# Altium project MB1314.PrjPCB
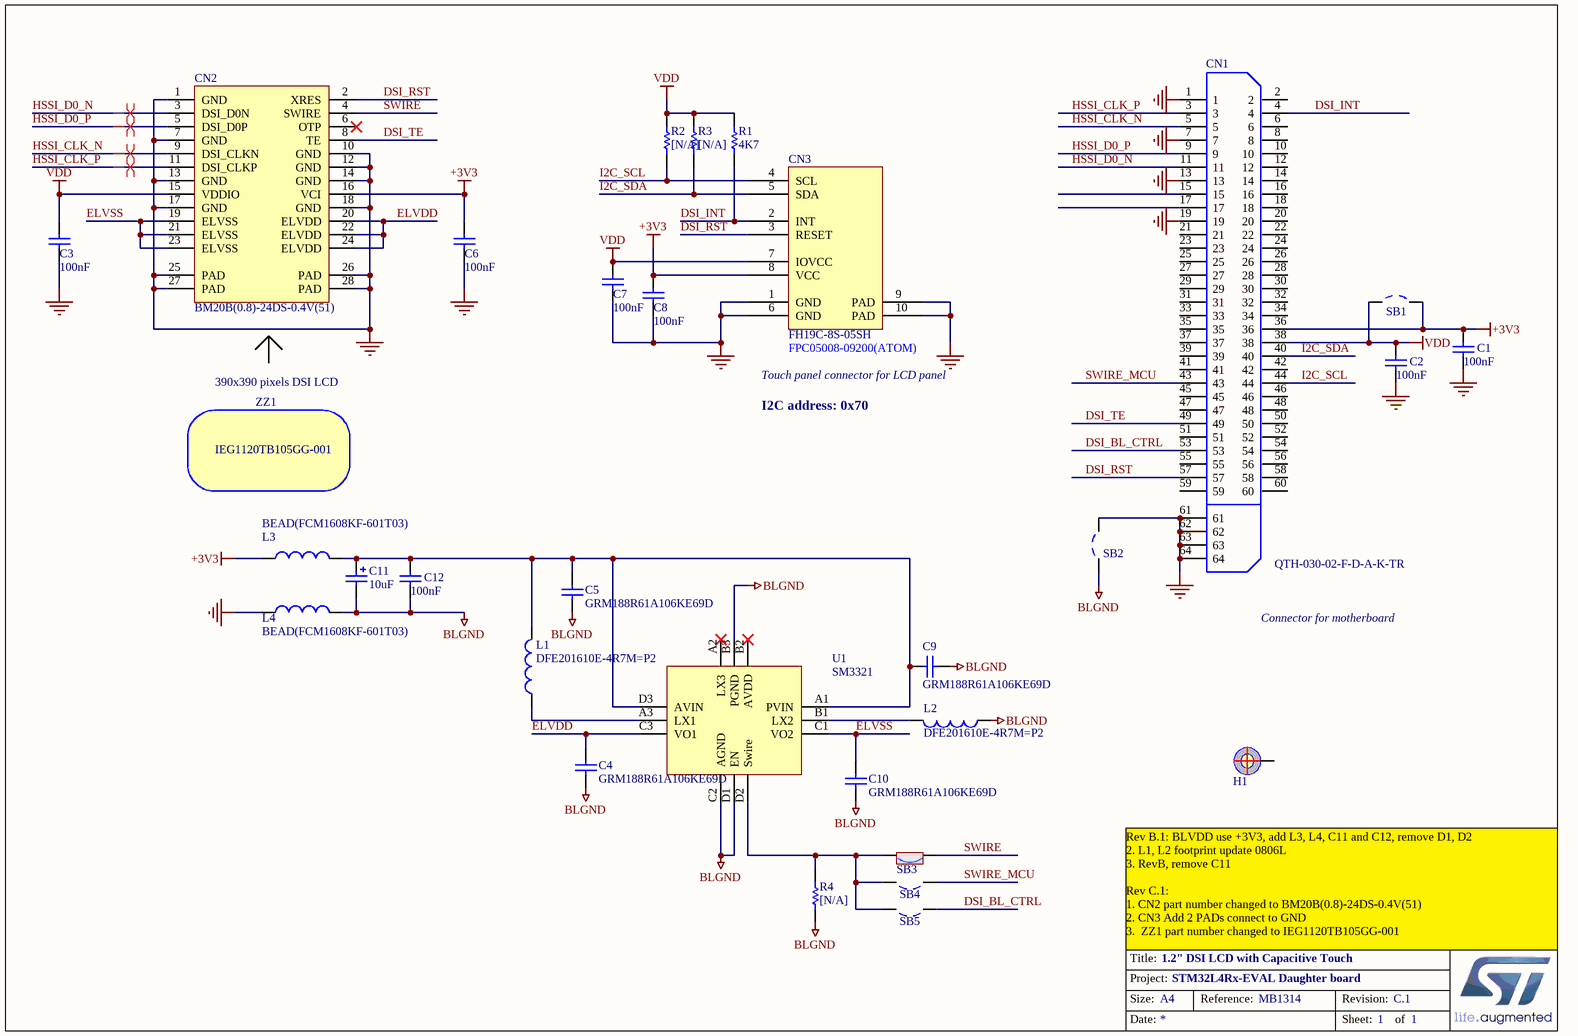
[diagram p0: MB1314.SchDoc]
1 sheet, 31 parts. Net scope: global (net labels, ports and power ports of the same name join across sheets).

## Sheet MB1314.SchDoc: 1.2" DSI LCD with Capacitive Touch
size A4; Date: 25-FEB-2015; Author: A.B; CompanyName: STMicroelectronics; Address1: 12, Rue Jules HOROWITZ; Address2: 38019 Grenoble; Address3: FRANCE; DocumentNumber: MB1314; Revision: C.1; SheetNumber: 1; SheetTotal: 1; Project: STM32L4Rx-EVAL Daughter board

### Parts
C1  100nF  [0603C]
C2  100nF  [0603C]
C3  100nF  [0603C]
C4  GRM188R61A106KE69D  [0603C]
C5  GRM188R61A106KE69D  [0603C]
C6  100nF  [0603C]
C7  100nF  [0603C]
C8  100nF  [0603C]
C9  GRM188R61A106KE69D  [0603C]
C10  GRM188R61A106KE69D  [0603C]
C11  10uF  [TAN-A]
C12  100nF  [0603C]
CN1  QTH-030-02-F-D-A-K-TR  [QTH-030-02-F-D-A]
CN2  BM20B(0.8)-24DS-0.4V(51)  [HRS_BM20B-24DS-0R4V]
CN3  FH19C-8S-05SH  [CONN_8SM_FPC05008-09200]
H1  POSITION HOLE  [HOLE_D3R5N]  (value not drawn)
L1  DFE201610E-4R7M=P2  [0806L]
L2  DFE201610E-4R7M=P2  [0806L]
L3  BEAD(FCM1608KF-601T03)  [0603L]
L4  BEAD(FCM1608KF-601T03)  [0603L]
R1  4K7  [0603R]
R2  [N/A]  [0603R]
R3  [N/A]  [0603R]
R4  [N/A]  [0603R]
SB1  Solder Bridge OFF  [SB_0603]  (value not drawn)
SB2  Solder Bridge OFF  [SB_0603]  (value not drawn)
SB3  Solder Bridge ON  [SB_0603]  (value not drawn)
SB4  Solder Bridge OFF  [SB_0603]  (value not drawn)
SB5  Solder Bridge OFF  [SB_0603]  (value not drawn)
U1  SM3321  [WLCSP12_0R4_1R53X1R74]
ZZ1  IEG1120TB105GG-001

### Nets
+3V3: C1.1 C6.2 C8.2 CN1.36 CN2.16(VCI) CN3.8(VCC) L3.1 SB1.2
BLGND: C4.2 C5.2 C9.2 C10.2 C11.2 C12.2 L2.1 L4.2 R4.1 SB2.1 U1.B3(PGND) U1.C2(AGND) U1.D1(EN)
GND: C1.2 C2.2 C3.1 C6.1 C7.1 C8.1 CN1.1 CN1.7 CN1.13 CN1.19 CN1.61 CN1.62 CN1.63 CN1.64 CN2.1(GND) CN2.7(GND) CN2.10(GND) CN2.12(GND) CN2.13(GND) CN2.14(GND) CN2.17(GND) CN2.18(GND) CN2.25(PAD) CN2.26(PAD) CN2.27(PAD) CN2.28(PAD) CN3.1(GND) CN3.6(GND) CN3.9(PAD) CN3.10(PAD) L4.1 SB2.2
VDD: C2.1 C3.2 C7.2 CN1.38 CN2.15(VDDIO) CN3.7(IOVCC) R1.1 R2.2 R3.2 SB1.1
DSI_BL_CTRL: CN1.53 SB5.1
DSI_INT: CN1.4 CN3.2(INT) R1.2
DSI_RST: CN1.57 CN2.2(XRES) CN3.3(RESET)
DSI_TE: CN1.49 CN2.8(TE)
ELVDD: C4.1 CN2.20(ELVDD) CN2.22(ELVDD) CN2.24(ELVDD) U1.C3(VO1)
ELVSS: C10.1 CN2.19(ELVSS) CN2.21(ELVSS) CN2.23(ELVSS) U1.C1(VO2)
HSSI_CLK_N: CN1.5 CN2.9(DSI_CLKN)
HSSI_CLK_P: CN1.3 CN2.11(DSI_CLKP)
HSSI_D0_N: CN1.11 CN2.3(DSI_D0N)
HSSI_D0_P: CN1.9 CN2.5(DSI_D0P)
I2C_SCL: CN1.44 CN3.4(SCL) R2.1
I2C_SDA: CN1.40 CN3.5(SDA) R3.1
SWIRE: CN2.4(SWIRE) SB3.1
SWIRE_MCU: CN1.43 SB4.1
NetC5_1: C5.1 C9.1 C11.1 C12.1 L1.2 L3.2 U1.A1(PVIN) U1.D3(AVIN)
NetL1_1: L1.1 U1.A3(LX1)
NetL2_2: L2.2 U1.B1(LX2)
NetR4_2: R4.2 SB3.2 SB4.2 SB5.2 U1.D2(Swire)

Not connected (* = marked no-connect by the designer): CN1 2 6 8 10 12 14 15 16 17 18 20 21 22 23 24 25 26 27 28 29 30 31 32 33 34 35 37 39 41 42 45 46 47 48 50 51 52 54 55 56 58 59 60; CN2 6(OTP)*; H1 1; U1 A2(LX3)* B2(AVDD)*

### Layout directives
differential pair: HSSI_CLK_N, HSSI_CLK_P, HSSI_D0_N, HSSI_D0_P

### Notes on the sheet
- 390x390 pixels DSI LCD
- Touch panel connector for LCD panel
- (near CN3) FPC05008-09200(ATOM)
- I2C address: 0x70
  IC:FT3267
- Connector for motherboard
- Rev B.1: BLVDD use +3V3, add L3, L4, C11 and C12, remove D1, D2
  2. L1, L2 footprint update 0806L
  3. RevB, remove C11
  Rev C.1:
  1. CN2 part number changed to BM20B(0.8)-24DS-0.4V(51)
  2. CN3 Add 2 PADs connect to GND
  3.  ZZ1 part number changed to IEG1120TB105GG-001

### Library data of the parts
C1 C2 C12 = Cap: Capacitor; Value: 10nF
C3 C6-C8 = CAP: Capacitor; Value: 100pF
C4 C5 C9 C10 = Cap: Capacitor; Manuf_1: TDK; Ordered by: Subcon; ECCN_US/EU: NA
C11 = Cap Pol1: Polarized Capacitor (Radial); Fitted: NO
CN1 = QTH-030-02-F-D-A: HIGH SPEED TERMINAL STRIP, .5mm PITCH, 60 PINS.; MANUFACTURER: SAMTEC
CN2 = 504208-2410: 4PINS 0.4MM CONNECTOR
CN3 = FH19C-8S-05SH: FH19C-8S-05SH 8PINS 0.5MM FPC CONNECTOR
H1 = POSITION HOLE: Fitted: NO
L1 L2 = Inductor: Manuf_1: Toko; Ordered by: Subcon; ECCN_US/EU: NA
L3 L4 = Inductor: Value: 100uH
R1 = Res1: Resistor; Value: 1K
R2-R4 = Res1: Resistor; Value: 1K; Ordered by: Subcon; Fitted: NO; ECCN_US/EU: NA
SB1 SB2 SB4 SB5 = SB_OFF: Fitted: NO; Ordered by: Subcon
SB3 = SB_ON: Fitted: YES; Ordered by: Subcon
U1 = SM3321: SM3321 AMOLED DRIVER
ZZ1 = BoM_Item: Frida LCD + Capacitive Touch Panel; Manuf_1: GVO; Ordered by: Subcon; ECCN_US/EU: EAR99/NEC; Fitted: YES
